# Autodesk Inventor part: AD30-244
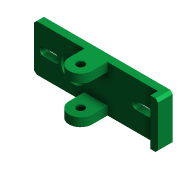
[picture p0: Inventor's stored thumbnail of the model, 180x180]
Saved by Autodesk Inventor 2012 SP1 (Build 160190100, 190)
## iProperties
Shininess: 0.0
Created: 2000-07
Part Number: AD30-244
User Status: RELEASED
Description: MOUNTING BRACKET
Document SubType Name: Modeling
Designer: Ron
Mass: 3.65232 g
Surface Area: 32.2452 cm^2
Volume: 3.65232 cm^3
Density: 1 g/cm^3
Material: Default
Density: 0.0
Volumn: 0.0
Area: 0.0
PropertySet Name: Model Information
Control State: 0
Master: False
Checked Out: False
Title: MOUNTING BRACKET
Author: Ron
Revision Number: A
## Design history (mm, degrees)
node "Extrusion1" dims "d2" = 3, "d3" = 0
  sketch "Sketch1"
    geometry: L1 (-25.4, 9.525)-(25.4, 9.525); L2 (25.4, 9.525)-(25.4, -9.525); L3 (25.4, -9.525)-(-25.4, -9.525); L4 (-25.4, -9.525)-(-25.4, 9.525); L5 (-25.4, -9.525)-(25.4, 9.525); 2 further points
    constraints: 10 end point, 2 parallel, 1 coincident, 1 horizontal, 1 midpoint, 1 perpendicular
    dimensions: "d0" = 19.05 distance of L3.end L1.start; "d1" = 50.8 distance of L1.start L1.end
node "Extrusion2" dims "d7" = 3, "d8" = 0
  sketch "Sketch2"
    geometry: L1 (0, -3)-(50.8, -3) reference; L2 (50.8, 0)-(0, 0) reference; L3 (0, 0)-(0, -3) reference; L4 (25.4, -3)-(25.4, -9.325); L5 (20.637, -9.325)-(20.637, -3); L6 (30.162, -9.325)-(30.162, -3); C1 r 1.587 at (25.4, -9.325); A1 r 4.763 centre (25.4, -9.325) between (20.637, -9.325) and (30.162, -9.325)
    constraints: 6 end point, 3 parallel, 2 centre point, 2 coincident, 2 point on circle, 2 point on line, 2 tangent, 1 midpoint
    dimensions: "d4" = 9.325 distance from line of L4.end L2; "d5" = 9.525 diameter of A1; "d6" = 3.175 diameter of C1
node "Extrusion3" dims "d10" = 3, "d11" = 0
  sketch "Sketch3"
    geometry: L1 (-25.4, -9.525)-(-25.4, 9.525) reference; L2 (-25.4, 6)-(25.4, 6); L3 (25.4, 6)-(25.4, -6); L4 (25.4, -6)-(-25.4, -6); L5 (-25.4, -6)-(-25.4, 6); L6 (25.4, 9.525)-(25.4, -9.525) reference; 1 further point
    constraints: 8 end point, 2 midpoint, 2 parallel, 1 collinear, 1 horizontal, 1 perpendicular
    dimensions: "d9" = 12 distance between parallel lines of L4 L2
node "Hole1" dims "d13" = 3.2, "d14" = 6.096, "d15" = 2, "d16" = 82 deg, "d17" = 8, "d18" = 118 deg
  sketch "Sketch4"
    geometry: L1 (25.4, 9.525)-(25.4, -9.525) reference; L2 (-25.4, -9.525)-(-25.4, 9.525) reference; L3 (25.4, -9.525)-(4.762, -9.525) reference; L4 (-25.4, 0)-(-19.05, 0); L5 (-19.05, 0)-(19.05, 0); L6 (19.05, 0)-(25.4, 0); 2 further points
    constraints: 6 end point, 2 coincident, 2 collinear, 2 midpoint, 1 parallel
    dimensions: "d12" = 38.1 distance of L4.end L5.end
node "End_mill_straight1"
  sketch "Sketch5"
    geometry: L1 (444.467, -58.438)-(449.467, -58.438); L2 (449.467, -55.238)-(444.467, -55.238); L3 (444.467, -56.838)-(449.467, -56.838); C1 r 1.6 at (446.967, -56.838) reference; C2 r 1.6 at (485.067, -56.838) reference; A1 r 1.6 centre (444.467, -56.838) between (444.467, -55.238) and (444.467, -58.438); A2 r 1.6 centre (449.467, -56.838) between (449.467, -58.438) and (449.467, -55.238); 1 further point
    constraints: 6 end point, 5 tangent, 4 point on circle, 2 centre point, 1 coincident, 1 midpoint, 1 parallel
    dimensions: "d19" = 1.6 radius of A2 (derived); "d21" = 5 distance of L3.start L3.end
node "End_mill_straight2" dims "d24" = 3.2, "d25" = 3, "d26" = 3 (derived)
  sketch "Sketch6"
    geometry: L1 (445.41, -11.672)-(450.41, -11.672); L2 (450.41, -8.472)-(445.41, -8.472); L3 (445.41, -10.072)-(450.41, -10.072); C1 r 1.6 at (447.91, -10.072); C2 r 1.6 at (447.91, -10.072) reference; A1 r 1.6 centre (445.41, -10.072) between (445.41, -8.472) and (445.41, -11.672); A2 r 1.6 centre (450.41, -10.072) between (450.41, -11.672) and (450.41, -8.472); 1 further point
    constraints: 6 end point, 4 point on circle, 4 tangent, 3 centre point, 2 coincident, 1 midpoint, 1 parallel
    dimensions: "d22" = 1.6 radius of A2 (= 0.5 x d24); "d23" = 5 distance of L3.start L3.end
node "Extrusion4" dims "d31" = 10, "d32" = 0
  sketch "Sketch7"
    geometry: L1 (0, 0)-(0, 3) reference; L2 (0, 0)-(3.175, 0); L3 (3.175, 0)-(3.175, 6.1); L4 (3.175, 6.1)-(0, 6.1); L5 (0, 6.1)-(0, 0)
    constraints: 8 end point, 2 parallel, 1 horizontal, 1 perpendicular
    dimensions: "d29" = 3.175 distance between parallel lines of L1 L3; "d37" = 6.1 distance of L2.end L3.end
chamfer "Chamfer2" distance "d38" = 1; stored, may be unused: second distance "d39" = 2, angle "d40" = 45 deg
sketch "Sketch9"
  geometry: L1 (25.4, 9.525)-(25.4, -9.525) reference; C1 r 5.25 at (-9.1, 0); A1 r 1.6 centre (-16.55, 0) between (-16.55, -1.6) and (-16.55, 1.6) reference
  constraints: 1 centre point, 1 horizontal alignment
  dimensions: "d41" = 34.5 distance from line of L1 C1.centre; "d42" = 10.5 diameter of C1
extrude "Extrusion6" cut sketch "Sketch9" distance "d43" = 1; taper "d44" = 0 deg
workaxis "Work Axis1"
body "Solid1"
